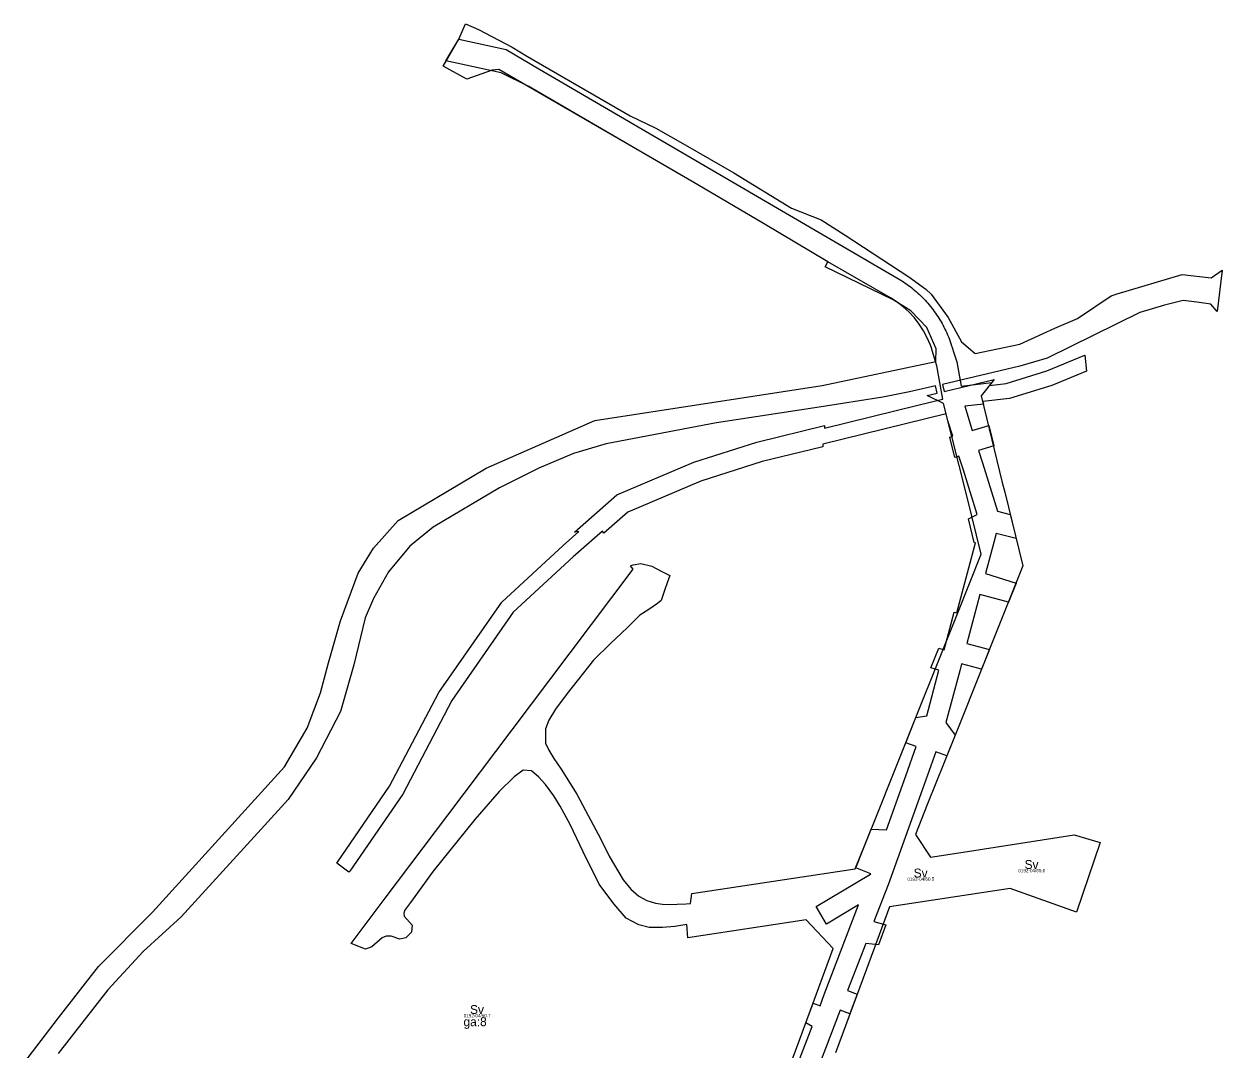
# Model space of a CAD drawing. Extents: x 140791 to 143631, y 6542790 to 6549933.
# Drawn here: x 142341.3 to 142812.6, y 6549529.4 to 6549932.7 of the extents above; entities that cross this region are included whole.
import ezdxf

# ---------------------------------------------------------------- set-up
doc = ezdxf.new("R2010")
doc.units = 0
for name, color, linetype in [('RATT Aktbeteckning för servitut', 7, 'Continuous'), ('RATT Beteckning för gemensammhetsanläggning', 7, 'Continuous'), ('RATT Beteckning för servitut', 7, 'Continuous'), ('RATT Gemensamhetsanläggningsgräns', 7, 'Continuous'), ('RATT Ledningsrättsgräns', 7, 'Continuous')]:
    doc.layers.add(name, color=color, linetype=linetype)

msp = doc.modelspace()

# ---------------------------------------------------------------- linework, layer by layer
at = {"layer": 'RATT Gemensamhetsanläggningsgräns'}
for points in [[(142341.26, 6549523.89), (142354.87, 6549541.62), (142370.52, 6549561.92), (142391.89, 6549583.21), (142443.75, 6549640.35), (142452.68, 6549655.59), (142457.9, 6549669.46), (142461.1, 6549681.34), (142465.82, 6549697.84), (142472.73, 6549716.62), (142478.77, 6549726.44), (142488.45, 6549737.27), (142523.06, 6549757.93), (142565.79, 6549776.67), (142655.31, 6549790.47), (142700.02, 6549799.83), (142700.16, 6549804.9), (142696.45, 6549813.24), (142690.16, 6549819.75), (142683.17, 6549824.09), (142656.42, 6549837.12), (142657.57, 6549839.13), (142632.18, 6549854.13), (142606.31, 6549869.31), (142580.39, 6549884.51), (142546.18, 6549904.3), (142528.05, 6549914.75), (142525.51, 6549914.45), (142515.47, 6549911), (142506.17, 6549916.11), (142512.34, 6549926.7), (142514.95, 6549932.65), (142520.1, 6549930.52), (142533.28, 6549923.57), (142539.38, 6549919.85)], [(142539.38, 6549919.85), (142579.71, 6549896.49), (142589.78, 6549891.7), (142601.35, 6549885.11), (142620.52, 6549874.11), (142643.17, 6549860.24), (142654.92, 6549855.64), (142664.35, 6549849.57), (142689.33, 6549833.15), (142696.07, 6549828.38), (142698.15, 6549826.38), (142704.87, 6549817.21), (142710.07, 6549807.61), (142715.5, 6549803.07), (142733.07, 6549806.74), (142746.82, 6549813.04), (142755.76, 6549816.75), (142768.99, 6549825.72), (142771.35, 6549826.55), (142796.93, 6549834.06), (142808.32, 6549832.82), (142812.59, 6549835.75), (142810.64, 6549819.51), (142808.14, 6549822.42), (142802.72, 6549823.22), (142797.3, 6549823.85), (142789.89, 6549822.03), (142780.25, 6549819.16), (142743.84, 6549801.14), (142733.05, 6549798.01), (142702.63, 6549790.88), (142703.3, 6549788.06), (142723.01, 6549792.78), (142717.87, 6549786.35), (142726.12, 6549752.31), (142727.15, 6549748.42), (142734.24, 6549719.43), (142722.46, 6549690.01), (142709.79, 6549658.38), (142696.76, 6549625.85), (142691.94, 6549613.82), (142697.93, 6549604.89), (142710.77, 6549606.89), (142754.38, 6549613.67), (142764.7, 6549610.59), (142755.32, 6549583.25), (142729.23, 6549592.48), (142681.73, 6549585.27), (142672.7, 6549560.85), (142660.55, 6549527.94)], [(142632.71, 6549496.13), (142646.45, 6549533.24), (142659.65, 6549568.89), (142648.98, 6549580.27), (142602.42, 6549573.11), (142602.08, 6549578.4), (142597.36, 6549577.6), (142592.48, 6549577.25), (142587.22, 6549577.15), (142583.09, 6549578.21), (142578.11, 6549580.84), (142573.33, 6549586.46), (142567.53, 6549594.28), (142561.29, 6549607.03), (142556.17, 6549617.75), (142552.27, 6549624.97), (142549.76, 6549629.02), (142546.49, 6549633.42), (142543.75, 6549636.39), (142540.99, 6549638.78), (142537.68, 6549639.12), (142534.15, 6549636.42), (142528.17, 6549630.68), (142518.63, 6549619.71), (142502.26, 6549599.36), (142493.27, 6549587.09), (142490.9, 6549583.91), (142490.7, 6549582.68), (142490.89, 6549581.66), (142493.98, 6549578.12), (142493.71, 6549575.43), (142491.52, 6549573.1), (142489.19, 6549572.6), (142485.72, 6549573.74), (142483.78, 6549573.76), (142482.24, 6549573.19), (142478.1, 6549569.62), (142475.6, 6549568.71), (142469.93, 6549570.88), (142483.42, 6549588.77), (142508.04, 6549621.45), (142533.31, 6549654.96), (142556.18, 6549685.3), (142580.94, 6549718.14), (142579.91, 6549719.49), (142580.92, 6549719.87), (142583.89, 6549720.42), (142588.23, 6549719.3), (142591.92, 6549717.39), (142595.31, 6549715.64), (142594.34, 6549712.83), (142593.43, 6549710.15), (142591.92, 6549705.87), (142590.52, 6549704.6), (142587.04, 6549702.36), (142583.58, 6549700.02), (142578.6, 6549695.09), (142572.02, 6549688.97), (142565.37, 6549682.34), (142554.9, 6549669.32), (142550.38, 6549663.04), (142547.78, 6549658.71), (142546.49, 6549655.39), (142546.5, 6549649.69), (142547.78, 6549646.9), (142549.76, 6549643.63), (142552.62, 6549639.46), (142558.79, 6549629.67), (142562.23, 6549623.27), (142568.14, 6549611.93), (142571.5, 6549605.2), (142577.05, 6549595.98), (142580.06, 6549592.23), (142583.09, 6549589.53), (142586.36, 6549587.86), (142589.73, 6549586.81), (142592.48, 6549586.44), (142595.72, 6549586.24), (142598.21, 6549586.34), (142601.71, 6549586.47), (142603.49, 6549586.64), (142604.03, 6549590.52), (142668.31, 6549600.32), (142675.82, 6549619.05), (142692.96, 6549661.84), (142708.63, 6549700.96), (142717.88, 6549724.04), (142712.26, 6549746.49), (142703, 6549783.35), (142696.65, 6549786.54), (142700.47, 6549787.39), (142699.8, 6549790.25), (142689.6, 6549787.96), (142679.15, 6549785.81), (142654.08, 6549781.91), (142613.76, 6549775.79), (142570.31, 6549767.48), (142557.44, 6549763.66), (142543.75, 6549757.95), (142528.34, 6549750.17), (142502.26, 6549734.72), (142493.08, 6549727.24), (142484.64, 6549717.12), (142478.77, 6549706.68), (142475.47, 6549699.02), (142471.01, 6549680.54), (142465.82, 6549662.16), (142456.41, 6549643.91), (142445.16, 6549627.54), (142434.61, 6549615.86), (142403.05, 6549581.35), (142388.09, 6549567.72), (142374.25, 6549552.66), (142354.65, 6549527.67)]]:
    msp.add_lwpolyline(points, dxfattribs=at)
at = {"layer": 'RATT Ledningsrättsgräns'}
for points in [[(142641.02, 6549511.36), (142651.3, 6549538.25), (142648.89, 6549539.65), (142651.77, 6549547.44), (142654.43, 6549546.42), (142656.11, 6549550.8), (142669.6, 6549586.07), (142657.01, 6549578.55), (142652.91, 6549585.42), (142674.33, 6549598.22), (142674.37, 6549598.34), (142668.48, 6549600.66), (142674.58, 6549615.9), (142680.55, 6549615.64), (142688.16, 6549636.92), (142692.28, 6549648.45), (142688.18, 6549649.91), (142692.15, 6549659.81), (142696.39, 6549660.53), (142701.17, 6549678.49), (142699.01, 6549679.07), (142698.04, 6549679.32), (142701.14, 6549687.07), (142703.3, 6549686.5), (142707.24, 6549701.28), (142708.22, 6549701.05), (142715.55, 6549728.57), (142715.11, 6549728.69), (142712.81, 6549737.92), (142716.27, 6549739.71), (142710.83, 6549757.1), (142709.1, 6549762.62), (142707.47, 6549762.1), (142705.46, 6549770.08), (142706.65, 6549770.46), (142704.73, 6549776.58), (142704.06, 6549779.22), (142655.59, 6549767.35), (142655.5, 6549766.3), (142650.65, 6549765.11), (142631.73, 6549760.48), (142607.51, 6549752.74), (142578.83, 6549740.55), (142569.44, 6549732.33), (142568.81, 6549733.11), (142557.35, 6549723.08), (142533.78, 6549701.29), (142509.56, 6549666.51), (142490.25, 6549629.64), (142469.41, 6549599.33), (142469.11, 6549598.93), (142464.31, 6549602.53), (142464.61, 6549602.93), (142485.1, 6549632.74), (142504.42, 6549669.63), (142529.23, 6549705.25), (142553.34, 6549727.54), (142559.53, 6549732.96), (142557.81, 6549732.78), (142574.52, 6549747.42), (142604.73, 6549760.25), (142629.56, 6549768.18), (142656.26, 6549774.72), (142656.16, 6549773.67), (142692.87, 6549782.66), (142702.57, 6549785.03), (142702.72, 6549785.07), (142700.43, 6549798.1), (142698.57, 6549804.25), (142698.36, 6549804.88), (142697.85, 6549806.31), (142696.6, 6549809.18), (142695.13, 6549811.94), (142693.44, 6549814.55), (142691.55, 6549817), (142689.46, 6549819.28), (142687.2, 6549821.37), (142684.78, 6549823.25), (142682.22, 6549824.9), (142657.57, 6549839.13), (142632.18, 6549854.13), (142606.31, 6549869.31), (142580.39, 6549884.51), (142539.82, 6549908.11), (142529.03, 6549913.44), (142507.25, 6549918.1), (142512.34, 6549926.7), (142531.01, 6549922.62), (142543.85, 6549915.02), (142686.18, 6549831.85), (142686.59, 6549831.61), (142687.25, 6549831.18), (142687.92, 6549830.74), (142688.57, 6549830.29), (142689.22, 6549829.83), (142689.86, 6549829.35), (142690.49, 6549828.86), (142691.11, 6549828.36), (142691.73, 6549827.86), (142692.34, 6549827.33), (142692.93, 6549826.8), (142693.52, 6549826.26), (142694.1, 6549825.7), (142694.67, 6549825.14), (142695.24, 6549824.56), (142695.79, 6549823.97), (142696.33, 6549823.38), (142696.86, 6549822.77), (142697.39, 6549822.16), (142697.9, 6549821.53), (142698.4, 6549820.89), (142698.89, 6549820.25), (142699.37, 6549819.6), (142699.84, 6549818.93), (142700.3, 6549818.26), (142700.75, 6549817.58), (142701.19, 6549816.9), (142701.61, 6549816.2), (142702.03, 6549815.5), (142702.43, 6549814.79), (142702.82, 6549814.07), (142703.2, 6549813.34), (142703.57, 6549812.61), (142703.92, 6549811.87), (142704.27, 6549811.13), (142704.6, 6549810.37), (142704.92, 6549809.62), (142705.22, 6549808.85), (142705.51, 6549808.08), (142705.8, 6549807.31), (142706.06, 6549806.53), (142706.08, 6549806.46), (142706.44, 6549805.34), (142707.11, 6549803.29), (142708.27, 6549799.73)], [(142708.27, 6549799.73), (142709.96, 6549790.13), (142722.04, 6549791.55), (142721.17, 6549790.45), (142727.68, 6549791.22), (142743.66, 6549796.14), (142758.62, 6549802.31), (142759.33, 6549796.11), (142745.69, 6549790.48), (142728.93, 6549785.33), (142718.47, 6549784.09), (142718.71, 6549783.11), (142711.34, 6549782.24), (142714.34, 6549772.66), (142720.87, 6549774.71), (142722.8, 6549766.69), (142716.8, 6549764.81), (142718.3, 6549760.02), (142724.25, 6549741.02), (142729.28, 6549739.69), (142731.61, 6549730.18), (142723.78, 6549732.26), (142722.95, 6549729.15), (142719.56, 6549716.45), (142731.54, 6549712.68), (142728.56, 6549705.24), (142717.37, 6549708.22), (142714.98, 6549699.25), (142712.22, 6549688.89), (142721.06, 6549686.53), (142717.98, 6549678.84), (142710.1, 6549680.94), (142709.38, 6549678.24), (142703.95, 6549657.85), (142707.61, 6549652.93), (142704.31, 6549644.71), (142699.99, 6549646.26), (142694.76, 6549631.61), (142681.19, 6549594), (142675.65, 6549579.5), (142680.39, 6549578.26), (142677.48, 6549570.38), (142672.51, 6549570.91), (142665.27, 6549552.36), (142669.04, 6549550.92), (142666.19, 6549543.22), (142662.34, 6549544.7), (142649.08, 6549510.05)]]:
    msp.add_lwpolyline(points, dxfattribs=at)

# ---------------------------------------------------------------- texts
at = {"layer": 'RATT Aktbeteckning för servitut'}
for s, p in [('0192-04/60.6', (142732.44, 6549598.94)), ('0192-04/60.5', (142688.8, 6549595.58)), ('0192-04/60.7', (142514.27, 6549541.88))]:
    msp.add_text(s, height=1.3, dxfattribs=at).set_placement(p)
at = {"layer": 'RATT Beteckning för gemensammhetsanläggning'}
msp.add_text('ga:8', height=3.5, dxfattribs=at).set_placement((142514.19, 6549538.37))
at = {"layer": 'RATT Beteckning för servitut'}
for p in [(142691.29, 6549596.88), (142734.92, 6549600.24), (142516.75, 6549543.18)]:
    msp.add_text('Sv', height=3.5, dxfattribs=at).set_placement(p)

doc.saveas('drawing.dxf')
